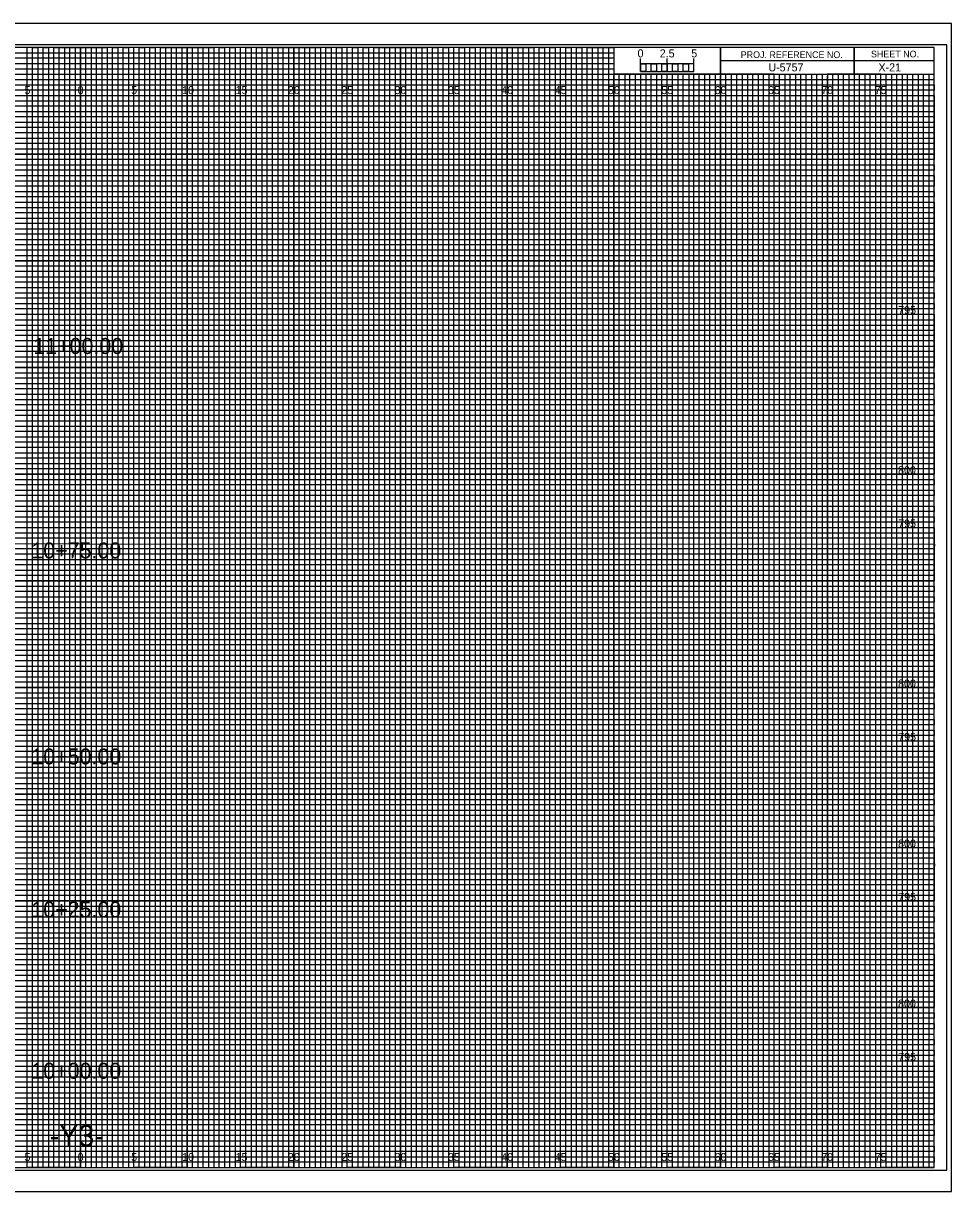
# Model space of a CAD drawing. Extents: x -7 to 162, y -2 to 107.
# Drawn here: x 74.6 to 161.7, y -2.3 to 107.3 of the extents above; entities that cross this region are included whole.
import ezdxf

# ---------------------------------------------------------------- set-up
doc = ezdxf.new("R2010")
doc.units = 0
for name, color, linetype in [('Prop XS Alignment Label', 7, 'Continuous'), ('Prop XS Bar Scale Labels', 7, 'Continuous'), ('Prop XS Elevation Labels', 7, 'Continuous'), ('Prop XS Offset Labels', 7, 'Continuous'), ('Prop XS Project Number', 7, 'Continuous'), ('Prop XS Sheet Number', 7, 'Continuous'), ('Prop XS Station Labels', 7, 'Continuous'), ('Sheet Cross Section CELL', 7, 'Continuous'), ('Sheet Cross Section Grid Major CELL', 7, 'Continuous'), ('Sheet Cross Section Grid Middle CELL', 7, 'Continuous'), ('Sheet Cross Section Grid Minor 1 CELL', 7, 'Continuous'), ('Sheet Cross Section Grid Minor 2 CELL', 7, 'Continuous'), ('Sheet Cross Section Scale CELL', 7, 'Continuous'), ('Sheet Cutting Line CELL', 7, 'Continuous'), ('Sheet DOT Grid CELL', 7, 'Continuous'), ('Sheet Plot Border Inside CELL', 7, 'Continuous'), ('Sheet Plot Border Outside CELL', 7, 'Continuous')]:
    doc.layers.add(name, color=color, linetype=linetype)

msp = doc.modelspace()

# ---------------------------------------------------------------- linework, layer by layer
at = {"layer": 'Sheet Cross Section CELL'}
for p, q in [((152.5, 105), (152.5, 102.5)), ((152.5, 102.5), (152.5, 105)), ((160, 103.75), (140, 103.75)), ((140, 103.75), (140, 102.5)), ((140, 102.5), (160, 102.5))]:
    msp.add_line(p, q, dxfattribs=at)
for points in [[(160, 105), (0, 105), (0, 0), (160, 0)], [(140, 105), (130, 105), (130, 102.52), (140, 102.52)], [(160, 105), (140, 105), (140, 102.5), (160, 102.5)]]:
    msp.add_lwpolyline(points, close=True, dxfattribs=at)
at = {"layer": 'Sheet Cross Section Grid Major CELL'}
for p, q in [((75, 105), (70, 105)), ((75, 0), (75, 105)), ((85, 105), (80, 105)), ((80, 105), (80, 0)), ((85, 0), (85, 105)), ((95, 105), (90, 105)), ((90, 105), (90, 0)), ((95, 0), (95, 105)), ((105, 105), (100, 105)), ((100, 105), (100, 0)), ((105, 0), (105, 105)), ((115, 105), (110, 105)), ((110, 105), (110, 0)), ((115, 0), (115, 105)), ((125, 105), (120, 105)), ((120, 105), (120, 0)), ((125, 0), (125, 105)), ((130, 105), (130, 0)), ((135, 0), (135, 102.5)), ((145, 102.5), (140, 102.5)), ((140, 102.5), (140, 0)), ((145, 0), (145, 102.5)), ((155, 102.5), (150, 102.5)), ((150, 102.5), (150, 0)), ((155, 0), (155, 102.5)), ((80, 0), (75, 0)), ((90, 0), (85, 0)), ((100, 0), (95, 0)), ((110, 0), (105, 0)), ((120, 0), (115, 0)), ((130, 0), (125, 0)), ((140, 0), (135, 0)), ((150, 0), (145, 0)), ((160, 0), (155, 0)), ((160, 0), (160, 0))]:
    msp.add_line(p, q, dxfattribs=at)
for points in [[(0, 100), (160, 100), (160, 95), (0, 95)], [(0, 90), (160, 90), (160, 85), (0, 85)], [(0, 80), (160, 80), (160, 75), (0, 75)], [(0, 70), (160, 70), (160, 65), (0, 65)], [(0, 60), (160, 60), (160, 55), (0, 55)], [(0, 50), (160, 50), (160, 45), (0, 45)], [(0, 40), (160, 40), (160, 35), (0, 35)], [(0, 30), (160, 30), (160, 25), (0, 25)], [(0, 20), (160, 20), (160, 15), (0, 15)], [(0, 10), (160, 10), (160, 5), (0, 5)]]:
    msp.add_lwpolyline(points, dxfattribs=at)
at = {"layer": 'Sheet Cross Section Grid Middle CELL'}
for points in [[(72.5, 0), (77.5, 0), (77.5, 105), (82.5, 105), (82.5, 0), (87.5, 0), (87.5, 105), (92.5, 105), (92.5, 0), (97.5, 0), (97.5, 105), (102.5, 105), (102.5, 0), (107.5, 0), (107.5, 105), (112.5, 105), (112.5, 0), (117.5, 0), (117.5, 105), (122.5, 105), (122.5, 0), (127.5, 0), (127.5, 105), (129.97, 105), (130, 105), (130, 102.5), (132.5, 102.5), (132.5, 0), (137.5, 0), (137.5, 102.5), (142.5, 102.5), (142.5, 0), (147.5, 0), (147.5, 102.5), (152.5, 102.5), (152.5, 0), (157.5, 0), (157.5, 102.5)], [(0, 102.5), (137.5, 102.5)], [(0, 92.5), (160, 92.5), (160, 97.5), (0, 97.5)], [(0, 82.5), (160, 82.5), (160, 87.5), (0, 87.5)], [(0, 72.5), (160, 72.5), (160, 77.5), (0, 77.5)], [(0, 62.5), (160, 62.5), (160, 67.5), (0, 67.5)], [(0, 52.5), (160, 52.5), (160, 57.5), (0, 57.5)], [(0, 42.5), (160, 42.5), (160, 47.5), (0, 47.5)], [(0, 32.5), (160, 32.5), (160, 37.5), (0, 37.5)], [(0, 22.5), (160, 22.5), (160, 27.5), (0, 27.5)], [(0, 12.5), (160, 12.5), (160, 17.5), (0, 17.5)], [(0, 2.5), (160, 2.5), (160, 7.5), (0, 7.5)]]:
    msp.add_lwpolyline(points, dxfattribs=at)
at = {"layer": 'Sheet Cross Section Grid Minor 1 CELL'}
for p, q in [((0, 104.5), (130, 104.5)), ((130, 104.5), (130, 103.99)), ((130, 103.99), (0, 103.99)), ((0, 103.5), (130, 103.5)), ((130, 102.95), (0, 102.95)), ((130, 103.5), (130, 102.95)), ((0, 102), (160, 102))]:
    msp.add_line(p, q, dxfattribs=at)
for points in [[(0, 101.5), (135, 101.5), (160, 101.5), (160, 101), (0, 101)], [(0, 100.5), (160, 100.5), (160, 99.5), (0, 99.5)], [(0, 99), (160, 99), (160, 98.5), (0, 98.49)], [(0, 98), (160, 98), (160, 97), (0, 97)], [(0, 96.5), (160, 96.5), (160, 96), (0, 96)], [(0, 95.5), (160, 95.5), (160, 94.5), (0, 94.5)], [(0, 94), (160, 94), (160, 93.5), (0, 93.5)], [(0, 93), (160, 93), (160, 92), (0, 92)], [(0, 91.5), (160, 91.5), (160, 91), (0, 91)], [(0, 90.5), (160, 90.5), (160, 89.5), (0, 89.5)], [(0, 89), (160, 89), (160, 88.5), (0, 88.5)], [(0, 88), (160, 88), (160, 86.98), (160, 86.5), (160, 86), (0, 86)], [(0, 87), (160, 87), (160, 86.5), (0, 86.5)], [(0, 85.5), (160, 85.5), (160, 84.5), (0, 84.52)], [(0, 84.52), (160, 84.5), (160, 84), (0, 84)], [(0, 83.5), (160, 83.5), (160, 83), (0, 83)], [(0, 82), (160, 82), (160, 81.5), (0, 81.5)], [(0, 81), (160, 81), (160, 80.5), (0, 80.5)], [(-0.04, 79.45), (160, 79.45), (160, 78.94), (-0.04, 78.94)], [(0, 78.5), (160, 78.5), (160, 78), (0, 78)], [(0, 77), (160, 77), (160, 76.5), (0, 76.5)], [(0, 76), (160, 76), (160, 75.5), (0, 75.5)], [(0, 74.5), (160, 74.5), (160, 74), (0, 74)], [(0, 73.5), (160, 73.5), (160, 73), (0, 73)], [(0, 72), (160, 72), (160, 71.5), (0, 71.5)], [(0, 71), (160, 71), (160, 70.5), (0, 70.5)], [(0, 69.5), (160, 69.5), (160, 68.99), (0, 69)], [(0, 68.5), (160, 68.5), (160, 68), (0, 68)], [(0, 67), (160, 67), (160, 66.5), (0, 66.5)], [(0, 66), (160, 66), (160, 65.5), (0, 65.5)], [(0, 64.5), (160, 64.5), (160, 64), (0, 64)], [(0, 63.5), (160, 63.5), (160, 63), (0, 63)], [(0, 62), (160, 62), (160, 61.5), (0, 61.5)], [(0, 61), (160, 61), (160, 60.5), (0, 60.5)], [(0, 59.5), (160, 59.5), (160, 59), (0, 59)], [(0, 58.5), (160.03, 58.45), (160, 58), (0, 58)], [(0, 57), (160, 57), (160, 56.5), (0, 56.5)], [(0, 56), (160, 56), (160, 55.5), (0, 55.5)], [(0, 54.5), (160, 54.5), (160, 54), (0, 54)], [(0, 53.5), (160, 53.5), (160, 53), (0, 53)], [(0, 52), (160, 52), (160, 51.5), (0, 51.5)], [(0, 51), (160, 51), (160, 50.5), (0, 50.5)], [(0, 49.5), (160, 49.5), (160, 49), (0, 49)], [(0, 48.5), (160, 48.5), (160, 48), (0, 48)], [(0, 47), (160, 47), (160, 46.5), (0, 46.5)], [(0, 46), (160, 46), (160, 45.5), (0, 45.5)], [(0, 44.5), (160, 44.5), (160, 44), (0, 44)], [(0, 43.5), (160, 43.5), (160, 43), (0, 43)], [(0, 42), (160, 42), (160, 41.5), (0, 41.5)], [(0, 41), (160, 41), (160, 40.5), (0, 40.5)], [(0, 39.5), (160, 39.5), (160, 38.99), (0, 39)], [(0, 38.5), (160, 38.5), (160, 38), (0, 38)], [(0, 37), (160, 37), (160, 36.5), (0, 36.5)], [(0, 36), (160, 36), (160, 35.5), (0, 35.5)], [(0, 34.5), (160, 34.5), (160, 34), (0, 34)], [(0, 33.5), (160, 33.5), (160, 33), (0, 33)], [(0, 32), (160, 32), (160, 31.5), (0, 31.5)], [(0, 31), (160, 31), (160, 30.5), (0, 30.5)], [(0, 29.5), (160, 29.5), (160, 29), (0, 29)], [(0, 28.5), (160.03, 28.46), (160, 28), (0, 28)], [(0, 27), (160, 27), (160, 26.5), (0, 26.5)], [(0, 26), (160, 26), (160, 25.5), (0, 25.5)], [(0, 24.5), (160, 24.5), (160, 24), (0, 24)], [(0, 23.5), (160, 23.5), (160, 23), (0, 23)], [(0, 22), (160, 22), (160, 21.5), (0, 21.5)], [(0, 21), (160, 21), (160, 20.5), (0, 20.5)], [(0, 19.5), (160, 19.5), (160, 19), (0, 19)], [(0, 18.5), (160, 18.5), (160, 18), (0, 18)], [(0, 17), (160, 17), (160, 16.5), (0, 16.5)], [(0, 16), (160, 16), (160, 15.5), (0, 15.5)], [(0, 14.5), (160, 14.5), (160, 14), (0, 14)], [(0, 13.5), (160, 13.5), (160, 13), (0, 13)], [(0, 12), (160, 12), (160, 11.5), (0, 11.5)], [(0, 11), (160, 11), (160, 10.5), (0, 10.5)], [(0, 9.5), (160, 9.5), (160, 9), (0, 9)], [(0, 8.5), (160, 8.5), (160, 8), (0, 8)], [(0, 7), (160, 7), (160, 6.5), (0, 6.5)], [(0, 6), (160, 6), (160, 5.5), (0, 5.5)], [(0, 4.5), (160, 4.5), (160, 4), (0, 4)], [(0, 3.5), (160, 3.5), (160, 3), (0, 3)], [(0, 2), (160, 2), (160, 1.5), (0, 1.5)], [(0, 1), (160, 1), (160, 0.5), (0, 0.5)]]:
    msp.add_lwpolyline(points, dxfattribs=at)
at = {"layer": 'Sheet Cross Section Grid Minor 2 CELL'}
for p, q in [((133.5, 102.5), (133, 102.5)), ((133, 102.5), (133, 0)), ((133.5, 0), (133.5, 102.5)), ((134.5, 102.5), (134, 102.5)), ((134, 102.5), (134, 0)), ((134.5, 0), (134.5, 102.5)), ((133, 0), (132.5, 0)), ((134, 0), (133.5, 0))]:
    msp.add_line(p, q, dxfattribs=at)
for points in [[(75, 0), (75.5, 0), (75.5, 105), (76, 105), (76, 0)], [(76, 0), (76.5, 0), (76.5, 105), (77, 105), (77, 0)], [(77.5, 0), (78, 0), (78, 105), (78.5, 105), (78.5, 0)], [(78.5, 0), (79, 0), (79, 105), (79.5, 105), (79.5, 0)], [(80, 0), (80.5, 0), (80.5, 105), (81, 105), (81, 0)], [(81, 0), (81.5, 0), (81.5, 105), (82, 105), (82, 0)], [(82.5, 0), (83, 0), (83, 105), (83.5, 105), (83.5, 0)], [(83.5, 0), (84, 0), (84, 105), (84.5, 105), (84.5, 0)], [(85, 0), (85.5, 0), (85.5, 105), (86, 105), (86, 0)], [(86, 0), (86.5, 0), (86.5, 105), (87, 105), (87, 0)], [(87.5, 0), (88, 0), (88, 105), (88.5, 105), (88.5, 0)], [(88.5, 0), (89, 0), (89, 105), (89.5, 105), (89.5, 0)], [(90, 0), (90.5, 0), (90.5, 105), (91, 105), (91, 0)], [(91, 0), (91.5, 0), (91.5, 105), (92, 105), (92, 0)], [(92.5, 0), (93, 0), (93, 105), (93.5, 105), (93.5, 0)], [(93.5, 0), (94, 0), (94, 105), (94.5, 105), (94.5, 0)], [(95, 0), (95.5, 0), (95.5, 105), (96, 105), (96, 0)], [(96, 0), (96.5, 0), (96.5, 105), (97, 105), (97, 0)], [(97.5, 0), (98, 0), (98, 105), (98.5, 105), (98.5, 0)], [(98.5, 0), (99, 0), (99, 105), (99.5, 105), (99.5, 0)], [(100, 0), (100.5, 0), (100.5, 105), (101, 105), (101, 0)], [(101, 0), (101.5, 0), (101.5, 105), (102, 105), (102, 0)], [(102.5, 0), (103, 0), (103, 105), (103.5, 105), (103.5, 0)], [(103.5, 0), (104, 0), (104, 105), (104.5, 105), (104.5, 0)], [(105, 0), (105.5, 0), (105.5, 105), (106, 105), (106, 0)], [(106, 0), (106.5, 0), (106.5, 105), (107, 105), (107, 0)], [(107.5, 0), (108, 0), (108, 105), (108.5, 105), (108.5, 0)], [(108.5, 0), (109, 0), (109, 105), (109.5, 105), (109.5, 0)], [(110, 0), (110.5, 0), (110.5, 105), (111, 105), (111, 0)], [(111, 0), (111.5, 0), (111.5, 105), (112, 105), (112, 0)], [(112.5, 0), (113, 0), (113, 105), (113.5, 105), (113.5, 0)], [(113.5, 0), (114, 0), (114, 105), (114.5, 105), (114.5, 0)], [(115, 0), (115.5, 0), (115.5, 105), (116, 105), (116, 0)], [(116, 0), (116.5, 0), (116.5, 105), (117, 105), (117, 0)], [(117.5, 0), (118, 0), (118, 105), (118.5, 105), (118.5, 0)], [(118.5, 0), (119, 0), (119, 105), (119.5, 105), (119.5, 0)], [(120, 0), (120.5, 0), (120.5, 105), (121, 105), (121, 0)], [(121, 0), (121.5, 0), (121.5, 105), (122, 105), (122, 0)], [(122.5, 0), (123, 0), (123, 105), (123.5, 105), (123.5, 0)], [(123.5, 0), (124, 0), (124, 105), (124.5, 105), (124.5, 0)], [(125, 0), (125.5, 0), (125.5, 105), (126, 105), (126, 0)], [(126, 0), (126.5, 0), (126.5, 105), (127, 105), (127, 0)], [(127.5, 0), (128, 0), (128, 105), (128.5, 105), (128.5, 0)], [(128.5, 0), (129, 0), (129, 105), (129.5, 105), (129.5, 0)], [(130, 0), (130.5, 0), (130.5, 102.5), (131.01, 102.5), (131.01, 0)], [(131, 0), (131.5, 0), (131.5, 102.5), (132, 102.5), (132, 0)], [(135, 0), (135.49, 0), (135.49, 102.5), (136, 102.5), (136, 0)], [(136, 0), (136.5, 0), (136.5, 102.5), (137.03, 102.5), (137.03, 0)], [(137.5, 0), (138, 0), (138, 102.5), (138.5, 102.5), (138.5, 0)], [(138.5, 0), (139, 0), (139, 102.5), (139.5, 102.5), (139.5, 0)], [(140, 0), (140.5, 0), (140.5, 102.5), (141, 102.5), (141, 0)], [(141, 0), (141.5, 0), (141.5, 102.5), (142, 102.5), (142, 0)], [(142.5, 0), (143, 0), (143, 102.5), (143.5, 102.5), (143.5, 0)], [(143.5, 0), (144, 0), (144, 102.5), (144.5, 102.5), (144.5, 0)], [(145, 0), (145.5, 0), (145.5, 102.5), (146, 102.5), (146, 0)], [(146, 0), (146.5, 0), (146.5, 102.5), (147, 102.5), (147, 0)], [(147.5, 0), (148, 0), (148, 102.5), (148.5, 102.5), (148.5, 0)], [(148.5, 0), (149, 0), (149, 102.5), (149.5, 102.5), (149.5, 0)], [(150, 0), (150.5, 0), (150.5, 102.5), (151, 102.5), (151, 0)], [(151, 0), (151.5, 0), (151.5, 102.5), (152, 102.5), (152, 0)], [(152.5, 0), (153, 0), (153, 102.5), (153.5, 102.5), (153.5, 0)], [(153.5, 0), (154, 0), (154, 102.5), (154.5, 102.5), (154.5, 0)], [(155, 0), (155.5, 0), (155.5, 102.5), (156, 102.5), (156, 0)], [(156, 0), (156.5, 0), (156.5, 102.5), (157, 102.5), (157, 0)], [(157.5, 0), (158, 0), (158, 102.5), (158.5, 102.5), (158.5, 0)], [(158.5, 0), (159, 0), (159, 102.5), (159.5, 102.5), (159.5, 0)]]:
    msp.add_lwpolyline(points, dxfattribs=at)
at = {"layer": 'Sheet Cross Section Scale CELL'}
for p, q in [((132.5, 102.75), (132.5, 103.95)), ((132.5, 103.45), (132.5, 103.95)), ((135, 102.75), (135, 103.95)), ((137.5, 102.75), (137.5, 103.95)), ((137.5, 103.45), (137.5, 103.95))]:
    msp.add_line(p, q, dxfattribs=at)
for points in [[(137.5, 103.45), (132.5, 103.45), (132.5, 102.75), (137.5, 102.75)], [(132.5, 103.45), (133, 103.45), (133, 102.75), (132.5, 102.75)], [(133.5, 103.45), (134, 103.45), (134, 102.75), (133.5, 102.75)], [(134.5, 103.45), (135, 103.45), (135, 102.75), (134.5, 102.75)], [(135.5, 103.45), (136, 103.45), (136, 102.75), (135.5, 102.75)], [(136.5, 103.45), (137, 103.45), (137, 102.75), (136.5, 102.75)]]:
    msp.add_lwpolyline(points, close=True, dxfattribs=at)
at = {"layer": 'Sheet Cutting Line CELL'}
for p, q in [((161.65, 107.25), (-6.7, 107.25)), ((-6.7, -2.25), (161.65, -2.25))]:
    msp.add_line(p, q, dxfattribs=at)
at = {"layer": 'Sheet DOT Grid CELL'}
for p, q in [((75, 0), (75, 105)), ((80, 0), (80, 105)), ((85, 0), (85, 105)), ((90, 0), (90, 105)), ((95, 0), (95, 105)), ((100, 0), (100, 105)), ((105, 0), (105, 105)), ((110, 0), (110, 105)), ((115, 0), (115, 105)), ((120, 0), (120, 105)), ((125, 0), (125, 105)), ((130, 0), (130, 102.34)), ((135, 0), (135, 102.34)), ((140, 0), (140, 102.34)), ((145, 0), (145, 102.34)), ((150, 0), (150, 102.34)), ((155, 0), (155, 102.34)), ((0, 100), (160, 100)), ((0, 95), (160, 95)), ((0, 90), (160, 90)), ((0, 85), (160, 85)), ((0, 80), (160, 80)), ((0, 75), (160, 75)), ((0, 70), (160, 70)), ((0, 65), (160, 65)), ((0, 60), (160, 60)), ((0, 55), (160, 55)), ((0, 50), (160, 50)), ((0, 45), (160, 45)), ((0, 40), (160, 40)), ((0, 35), (160, 35)), ((0, 30), (160, 30)), ((0, 25), (160, 25)), ((0, 20), (160, 20)), ((0, 15), (160, 15)), ((0, 10), (160, 10)), ((0, 5), (160, 5))]:
    msp.add_line(p, q, dxfattribs=at)
at = {"layer": 'Sheet Plot Border Inside CELL'}
msp.add_lwpolyline([(-5.4, -0.25), (161.2, -0.25), (161.2, 105.25), (-5.4, 105.25)], close=True, dxfattribs=at)
at = {"layer": 'Sheet Plot Border Outside CELL'}
msp.add_lwpolyline([(-6.7, -2.25), (161.65, -2.25), (161.65, 107.25), (-6.7, 107.25)], close=True, dxfattribs=at)

# ---------------------------------------------------------------- texts
at = {"layer": 'Prop XS Alignment Label'}
msp.add_text('-Y3-', height=2, dxfattribs=at).set_placement((77.12, 2))
at = {"layer": 'Prop XS Bar Scale Labels'}
for s, p in [('2.5', (134.29, 104.06)), ('5', (137.24, 104.06))]:
    msp.add_text(s, height=0.75, dxfattribs=at).set_placement(p)
at = {"layer": 'Prop XS Elevation Labels'}
for s, p in [('795', (156.64, 80)), ('800', (156.63, 65)), ('795', (156.64, 60)), ('800', (156.63, 45)), ('795', (156.64, 40)), ('800', (156.63, 30)), ('795', (156.64, 25)), ('800', (156.63, 15)), ('795', (156.64, 10))]:
    msp.add_text(s, height=0.75, dxfattribs=at).set_placement(p)
at = {"layer": 'Prop XS Offset Labels'}
for s, p in [('5', (74.74, 100.62)), ('0', (79.73, 100.62)), ('0', (79.73, 100.62)), ('5', (84.74, 100.62)), ('10', (89.52, 100.62)), ('15', (94.53, 100.62)), ('20', (99.43, 100.62)), ('25', (104.44, 100.62)), ('30', (109.43, 100.62)), ('35', (114.44, 100.62)), ('40', (119.43, 100.62)), ('45', (124.44, 100.62)), ('50', (129.43, 100.62)), ('55', (134.44, 100.62)), ('60', (139.43, 100.62)), ('65', (144.44, 100.62)), ('70', (149.43, 100.62)), ('75', (154.44, 100.62)), ('5', (74.74, 0.62)), ('0', (79.73, 0.62)), ('0', (79.73, 0.62)), ('5', (84.74, 0.62)), ('10', (89.52, 0.62)), ('15', (94.53, 0.62)), ('20', (99.43, 0.62)), ('25', (104.44, 0.62)), ('30', (109.43, 0.62)), ('35', (114.44, 0.62)), ('40', (119.43, 0.62)), ('45', (124.44, 0.62)), ('50', (129.43, 0.62)), ('55', (134.44, 0.62)), ('60', (139.43, 0.62)), ('65', (144.44, 0.62)), ('70', (149.43, 0.62)), ('75', (154.44, 0.62))]:
    msp.add_text(s, height=0.75, dxfattribs=at).set_placement(p)
at = {"layer": 'Prop XS Project Number'}
msp.add_text('U-5757', height=0.75, dxfattribs=at).set_placement((144.47, 102.75))
at = {"layer": 'Prop XS Sheet Number'}
msp.add_text('X-21', height=0.75, dxfattribs=at).set_placement((154.79, 102.75))
at = {"layer": 'Prop XS Station Labels'}
for s, p in [('11+00.00', (75.57, 76.26)), ('10+75.00', (75.39, 57.1)), ('10+50.00', (75.39, 37.79)), ('10+25.00', (75.39, 23.44)), ('10+00.00', (75.39, 8.33))]:
    msp.add_text(s, height=1.5, dxfattribs=at).set_placement(p)
at = {"layer": 'Sheet Cross Section CELL'}
for s, p in [('PROJ. REFERENCE NO.', (141.88, 104)), ('SHEET NO.', (154.09, 104.06))]:
    msp.add_text(s, height=0.625, dxfattribs=at).set_placement(p)
at = {"layer": 'Sheet Cross Section Scale CELL'}
msp.add_text('0', height=0.75, dxfattribs=at).set_placement((132.21, 104.06))

doc.saveas('drawing.dxf')
